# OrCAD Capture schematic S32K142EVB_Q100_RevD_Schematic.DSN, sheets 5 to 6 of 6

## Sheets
5 5. Power Supply/SWD: size C
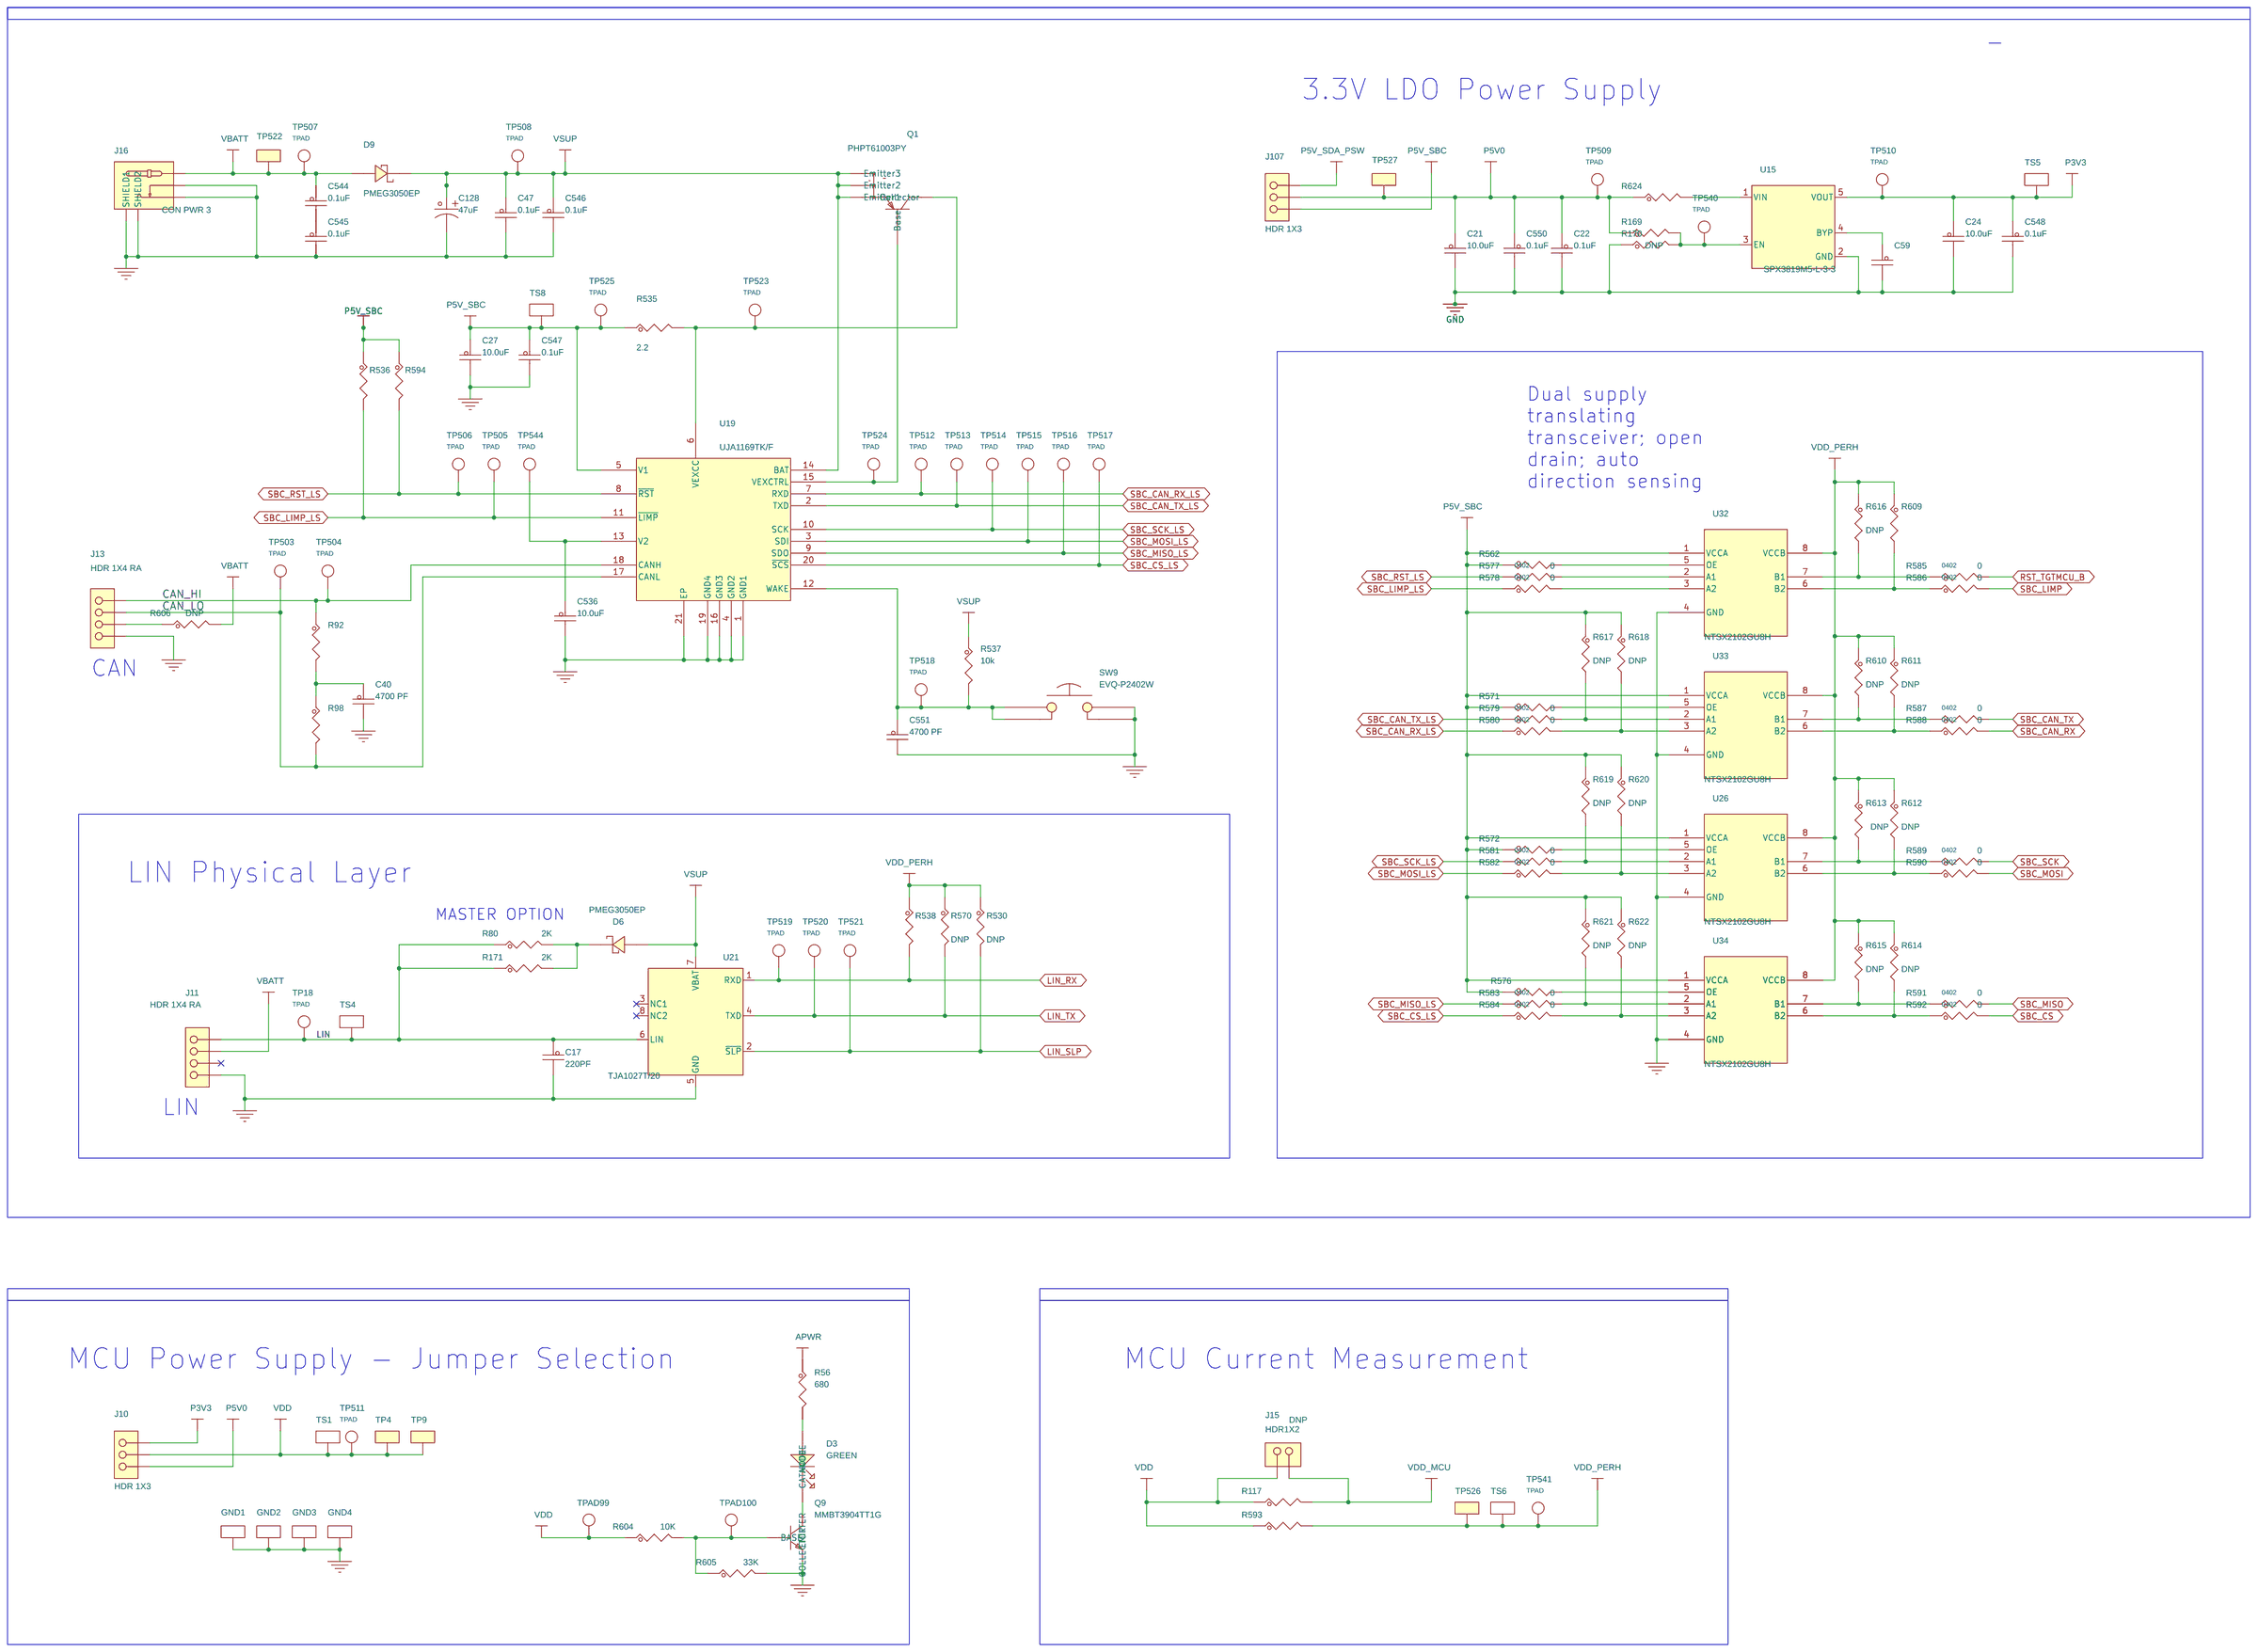
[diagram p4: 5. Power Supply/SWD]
6 6. I/O Headers: size C
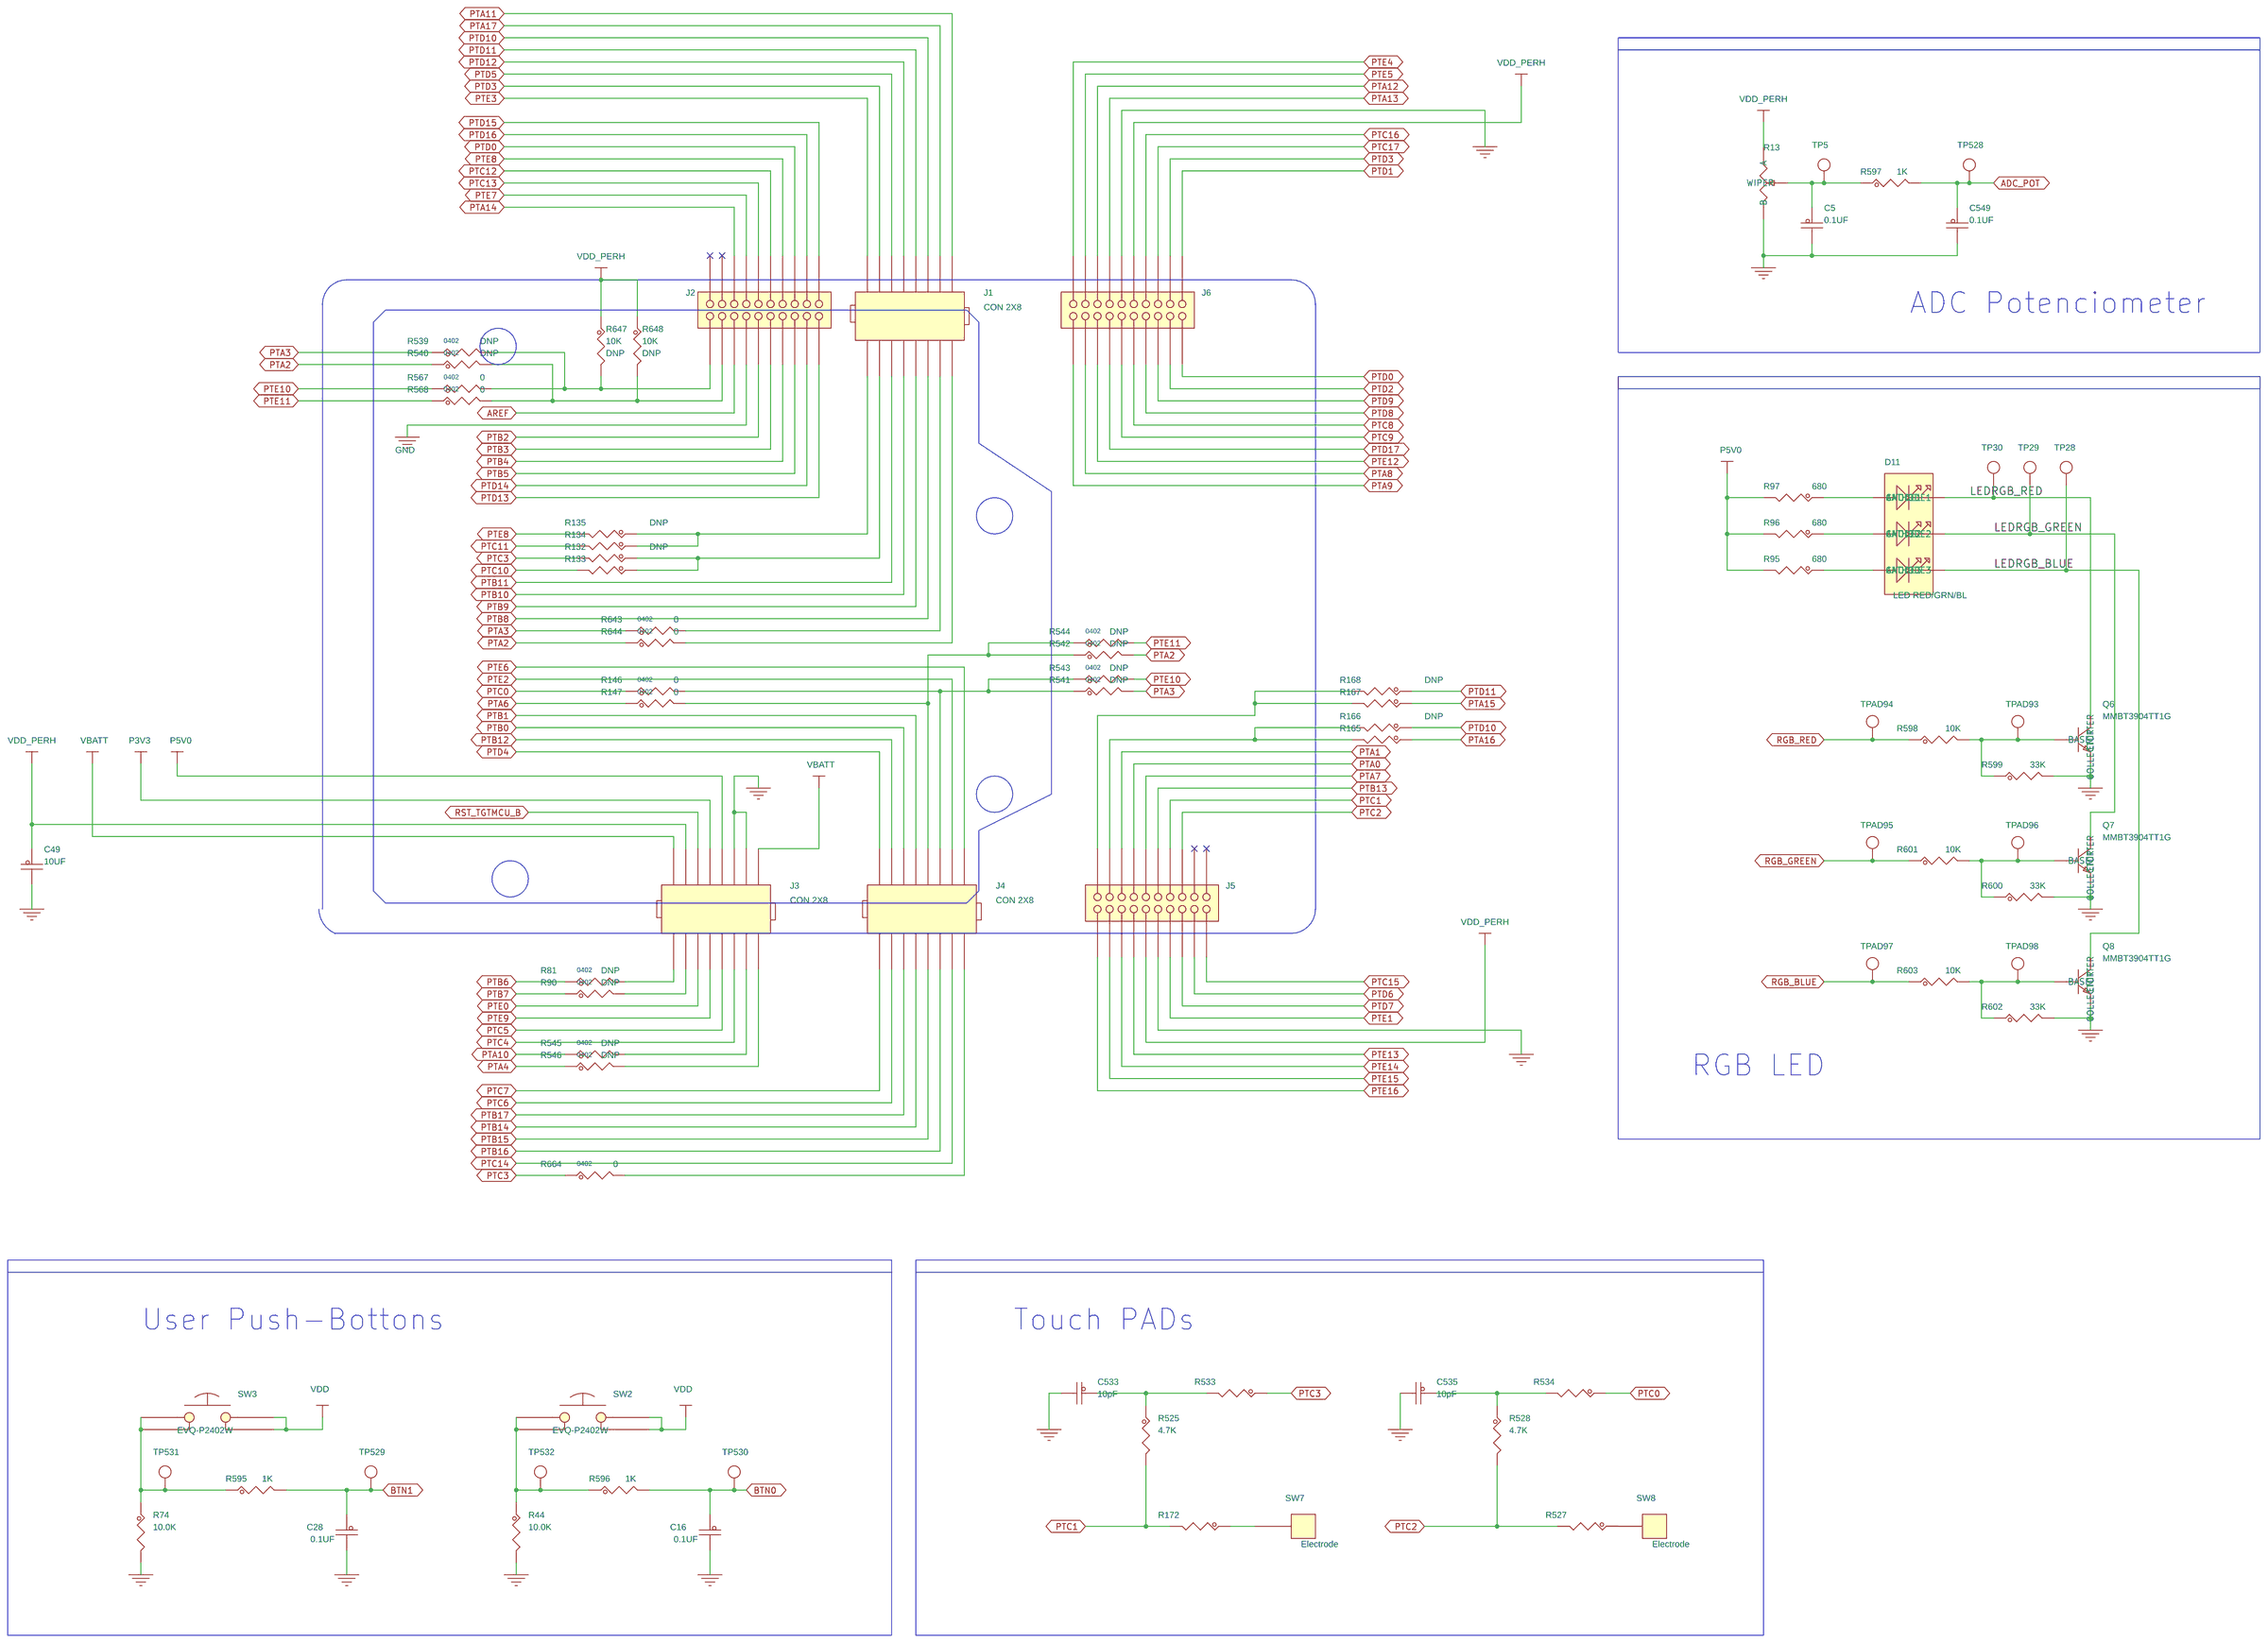
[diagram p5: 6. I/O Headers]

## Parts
sheet 5. Power Supply/SWD
C17  220PF  [CC0603_OV]
C21  10.0uF  [CC0805_OV]
C22  0.1uF  [CC0402_25]
C24  10.0uF  [CC0805_OV]
C27  10.0uF  [CC0805_OV]
C40  4700 PF  [CC0603_OV]
C47  0.1uF  [CC0402_25]
C59  0.01UF  [CC0402_25]
C128  47uF  [cce6p8x6p8]
C536  10.0uF  [CC0805_OV]
C544  0.1uF  [CC0402_25]
C545  0.1uF  [CC0402_25]
C546  0.1uF  [CC0402_25]
C547  0.1uF  [CC0402_25]
C548  0.1uF  [CC0402_25]
C550  0.1uF  [CC0402_25]
C551  4700 PF  [CC0603_OV]
D3  GREEN  [LED_0603]
D6  PMEG3050EP  [sod-128]
D9  PMEG3050EP  [sod-128]
GND1  5006  [tp_th_063]
GND2  5006  [tp_th_063]
GND3  5006  [tp_th_063]
GND4  5006  [tp_th_063]
J10  HDR 1X3  [HDR103_A]
J11  HDR 1X4 RA  [con_hdr_4m_100_th_ra]
J13  HDR 1X4 RA  [con_hdr_4m_100_th_ra]
J15  HDR1X2  [hdr1x2_5p48x2p69]
J16  CON PWR 3  [con3_pwr_jack_th_pj051a]
J107  HDR 1X3  [HDR103_A]
Q1  PHPT61003PY  [LFPAK5_1P27_5X4]
Q9  MMBT3904TT1G  [sc_75]
R56  680  [RC0603_OV]
R80  2K  [RC0805_OV]
R92  60.4  [RC1206_OV]
R98  60.4  [RC1206_OV]
R117  0  [RC0603_OV]
R169  0  [RC0402_25]
R170  0  [RC0402_25]
R171  2K  [RC0805_OV]
R530  4.7K  [RC0603_OV]
R535  2.2  [RC0805_OV]
R536  4.7K  [RC0603_OV]
R537  10k  [RC0805_OV]
R538  4.7K  [RC0603_OV]
R562  4.7K  [RC0402_25]
R570  4.7K  [RC0603_OV]
R571  4.7K  [RC0402_25]
R572  4.7K  [RC0402_25]
R576  4.7K  [RC0402_25]
R577  0  [RC0402_25]
R578  0  [RC0402_25]
R579  0  [RC0402_25]
R580  0  [RC0402_25]
R581  0  [RC0402_25]
R582  0  [RC0402_25]
R583  0  [RC0402_25]
R584  0  [RC0402_25]
R585  0  [RC0402_25]
R586  0  [RC0402_25]
R587  0  [RC0402_25]
R588  0  [RC0402_25]
R589  0  [RC0402_25]
R590  0  [RC0402_25]
R591  0  [RC0402_25]
R592  0  [RC0402_25]
R593  0  [RC0603_OV]
R594  4.7K  [RC0603_OV]
R604  10K  [RC0402_25]
R605  33K  [RC0402_25]
R606  0  [RC0603_OV]
R609  10.0K  [RC0402_25]
R610  10.0K  [RC0402_25]
R611  10.0K  [RC0402_25]
R612  10.0K  [RC0402_25]
R613  10.0K  [RC0402_25]
R614  10.0K  [RC0402_25]
R615  10.0K  [RC0402_25]
R616  10.0K  [RC0402_25]
R617  10.0K  [RC0402_25]
R618  10.0K  [RC0402_25]
R619  10.0K  [RC0402_25]
R620  10.0K  [RC0402_25]
R621  10.0K  [RC0402_25]
R622  10.0K  [RC0402_25]
R624  0  [RC0603_OV]
SW9  EVQ-P2402W  [sw4_spst_4p8X3p6_2p5]
TP4  TEST_POINT  [tp_th_063]
TP9  TEST_POINT  [tp_th_063]
TP18  TPAD_030  [TPAD_030]
TP503  TPAD_030  [TPAD_030]
TP504  TPAD_030  [TPAD_030]
TP505  TPAD_030  [TPAD_030]
TP506  TPAD_030  [TPAD_030]
TP507  TPAD_030  [TPAD_030]
TP508  TPAD_030  [TPAD_030]
TP509  TPAD_030  [TPAD_030]
TP510  TPAD_030  [TPAD_030]
TP511  TPAD_030  [TPAD_030]
TP512  TPAD_030  [TPAD_030]
TP513  TPAD_030  [TPAD_030]
TP514  TPAD_030  [TPAD_030]
TP515  TPAD_030  [TPAD_030]
TP516  TPAD_030  [TPAD_030]
TP517  TPAD_030  [TPAD_030]
TP518  TPAD_030  [TPAD_030]
TP519  TPAD_030  [TPAD_030]
TP520  TPAD_030  [TPAD_030]
TP521  TPAD_030  [TPAD_030]
TP522  TEST_POINT  [tp_th_063]
TP523  TPAD_030  [TPAD_030]
TP524  TPAD_030  [TPAD_030]
TP525  TPAD_030  [TPAD_030]
TP526  TEST_POINT  [tp_th_063]
TP527  TEST_POINT  [tp_th_063]
TP540  TPAD_030  [TPAD_030]
TP541  TPAD_030  [TPAD_030]
TP544  TPAD_030  [TPAD_030]
TPAD99  TPAD_030  [TPAD_030]
TPAD100  TPAD_030  [TPAD_030]
TS1  TESTLOOP  [testpoint_135_070mil]
TS4  TESTLOOP  [testpoint_135_070mil]
TS5  TESTLOOP  [testpoint_135_070mil]
TS6  TESTLOOP  [testpoint_135_070mil]
TS8  TESTLOOP  [testpoint_135_070mil]
U15  SPX3819M5-L-3-3  [SOT23_5S]
U19  UJA1169TK/F  [son20_0p5_3p6x5p6]
U21  TJA1027T/20  [so8_1p27_4x5]
U26  NTSX2102GU8H  [xqfn8_1p45x1p25mm]
U32  NTSX2102GU8H  [xqfn8_1p45x1p25mm]
U33  NTSX2102GU8H  [xqfn8_1p45x1p25mm]
U34  NTSX2102GU8H  [xqfn8_1p45x1p25mm]
sheet 6. I/O Headers
C5  0.1UF  [CC0402_25]
C16  0.1UF  [CC0402_25]
C28  0.1UF  [CC0402_25]
C49  10UF  [CC0805_OV]
C533  10pF  [CC0603_OV]
C535  10pF  [CC0603_OV]
C549  0.1UF  [CC0402_25]
D11  LED RED/GRN/BL  [led6_5x6mm]
J1  CON 2X8  [con2x8_2p54_th]
J2  CON 2X10  [con20_2p54_th]
J3  CON 2X8  [con2x8_2p54_th]
J4  CON 2X8  [con2x8_2p54_th]
J5  CON 2X10  [con20_2p54_th]
J6  CON 2X10  [con20_2p54_th]
Q6  MMBT3904TT1G  [sc_75]
Q7  MMBT3904TT1G  [sc_75]
Q8  MMBT3904TT1G  [sc_75]
R13  5K  [pot3_3352t]
R44  10.0K  [RC0402_25]
R74  10.0K  [RC0402_25]
R81  0  [RC0402_25]
R90  0  [RC0402_25]
R95  680  [RC0603_OV]
R96  680  [RC0603_OV]
R97  680  [RC0603_OV]
R132  0  [RC0603_OV]
R133  0  [RC0603_OV]
R134  0  [RC0603_OV]
R135  0  [RC0603_OV]
R146  0  [RC0402_25]
R147  0  [RC0402_25]
R165  0  [RC0603_OV]
R166  0  [RC0603_OV]
R167  0  [RC0603_OV]
R168  0  [RC0603_OV]
R172  0  [RC0603_OV]
R525  4.7K  [RC0603_OV]
R527  0  [RC0603_OV]
R528  4.7K  [RC0603_OV]
R533  0  [RC0603_OV]
R534  0  [RC0603_OV]
R539  0  [RC0402_25]
R540  0  [RC0402_25]
R541  0  [RC0402_25]
R542  0  [RC0402_25]
R543  0  [RC0402_25]
R544  0  [RC0402_25]
R545  0  [RC0402_25]
R546  0  [RC0402_25]
R567  0  [RC0402_25]
R568  0  [RC0402_25]
R595  1K  [RC0603_OV]
R596  1K  [RC0603_OV]
R597  1K  [RC0603_OV]
R598  10K  [RC0402_25]
R599  33K  [RC0402_25]
R600  33K  [RC0402_25]
R601  10K  [RC0402_25]
R602  33K  [RC0402_25]
R603  10K  [RC0402_25]
R643  0  [RC0402_25]
R644  0  [RC0402_25]
R647  10K  [RC0402_25]
R648  10K  [RC0402_25]
R664  0  [RC0402_25]
SW2  EVQ-P2402W  [sw4_spst_4p8X3p6_2p5]
SW3  EVQ-P2402W  [sw4_spst_4p8X3p6_2p5]
SW7  Electrode  [electrode_sq_15mm]
SW8  Electrode  [electrode_sq_15mm]
TP5  TPAD_030  [TPAD_030]
TP28  TPAD_030  [TPAD_030]
TP29  TPAD_030  [TPAD_030]
TP30  TPAD_030  [TPAD_030]
TP528  TPAD_030  [TPAD_030]
TP529  TPAD_030  [TPAD_030]
TP530  TPAD_030  [TPAD_030]
TP531  TPAD_030  [TPAD_030]
TP532  TPAD_030  [TPAD_030]
TPAD93  TPAD_030  [TPAD_030]
TPAD94  TPAD_030  [TPAD_030]
TPAD95  TPAD_030  [TPAD_030]
TPAD96  TPAD_030  [TPAD_030]
TPAD97  TPAD_030  [TPAD_030]
TPAD98  TPAD_030  [TPAD_030]

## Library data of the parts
C17 = CAP_NP: CAP CER 220PF 50V 10% X7R 0603; AGILE_PN: 150-75200; CAD_APPROVED: Yes; FPLIST: CC0603_OV,CC0603,0603_CC; HEIGHT: 0.9652MM; MFG_NAME01: KEMET; MFG_PN01: C0603C221K5RAC; ROHS: Yes; Tolerance: 10%; VOLTAGE: 50V
C21 C24 C27 C536 = CAP_NP: CAP CER 10UF 16V 10% X7R 0805; AGILE_PN: 150-30139; CAD_APPROVED: Yes; FPLIST: CC0805_OV,CC0805,0805_CC; HEIGHT: 1.27mm; MFG_NAME01: CAPAX TECHNOLOGIES INC.; MFG_PN01: 0805X106K160SNT; ROHS: Yes; Tolerance: 10%; VOLTAGE: 16V
C22 C548 C550 = CAP_NP: CAP CER 0.1uF 50V 10% X7R 0402; AGILE_PN: 150-79069; CAD_APPROVED: Yes; FPLIST: CC0402_25,CC0402_HD,0402_CC; HEIGHT: 0.9 MM; MFG_NAME01: MURATA; MFG_PN01: GCM188R71H104KA57D; ROHS: Yes; Tolerance: 10%; VOLTAGE: 50V
C40 C551 = CAP_NP: CAP CER 4700PF 50V 5% X7R 0603; AGILE_PN: 150-30045; CAD_APPROVED: Yes; FPLIST: CC0603_OV,CC0603,0603_CC; HEIGHT: 1.0MM; MFG_NAME01: AVX; MFG_PN01: 06035C472JAT2A; ROHS: Yes; Tolerance: 5%; VOLTAGE: 50V
C47 C544-C547 = CAP_NP: CAP CER 0.1uF 50V 10% X7R 0402; AGILE_PN: 150-79069; CAD_APPROVED: Yes; FPLIST: CC0402_25,CC0402_HD,0402_CC; HEIGHT: 0.9 MM; MFG_NAME01: TDK; MFG_PN01: C1608X8R1E104K; ROHS: Yes; Tolerance: 10%; VOLTAGE: 50V
C59 = CAP_NP: CAP CER 0.01UF 16V 20% X7R 0402; AGILE_PN: 150-30082; CAD_APPROVED: Yes; FPLIST: CC0402_25,CC0402_HD,0402_CC; HEIGHT: 0.56MM; MFG_NAME01: AVX; MFG_PN01: 0402YC103MAT2A; ROHS: Yes; TOL: 20%; Tolerance: 20%; VOLTAGE: 16V
C128 = CAP_POL: CAP ALEL 47uF 25V 20% -- SMT; AGILE_PN: 150-79138; CAD_APPROVED: Yes; HEIGHT: 6.1MM; MFG_NAME01: NICHICON; MFG_PN01: UUD1E470MCL1GS; ROHS: Yes; Tolerance: 20%; VOLTAGE: 25V
D3 = LED: LED GRN SGL 25MA 0603; AGILE_PN: 370-76549; CAD_APPROVED: Yes; HEIGHT: 0.85MM; MFG_NAME01: KINGBRIGHT; MFG_PN01: KPT-1608SGC; ROHS: Yes
D6 D9 = DIODE_SCHTKY: DIODE SCH RECT 5A 30V AEC-Q101 SOD128; AGILE_PN: 480-78776; CAD_APPROVED: Yes; HEIGHT: 1.1 MM; MFG_NAME01: NXP SEMICONDUCTORS; MFG_PN01: PMEG3050EP,115; ROHS: Yes
GND1 GND2 = TEST_POINT_3: TEST POINT BLK 70X220 MIL TH; AGILE_PN: 210-30155; CAD_APPROVED: Yes; HEIGHT: 5.6MM; MFG_NAME01: Keystone Electronics; ROHS: Yes
GND3 GND4 = TEST_POINT_3: TEST POINT BLK 70X220 MIL TH; AGILE_PN: 210-30155; ASSY_OPT: DNP; CAD_APPROVED: Yes; HEIGHT: 5.6MM; MFG_NAME01: Keystone Electronics; ROHS: Yes
J10 = CONN_HDR_3X1: HDR 1X3 TH 2.54MM SP 344H AU 118L; AGILE_PN: 210-80732; CAD_APPROVED: Yes; HEIGHT: 8.74MM; MFG_NAME01: Shenzhen JXT Technology Co., Ltd.; MFG_PN01: JT254-D180-103-001; ROHS: Yes
J11 J13 = CONN_HDR_4X1: HDR 1X4 TH RA 100MIL SP 268H AU 124L; AGILE_PN: 210-79929; CAD_APPROVED: Yes; HEIGHT: 6.81MM; MFG_NAME01: MOLEX; MFG_PN01: 0022122041; ROHS: Yes
J15 = CONN_HDR_2X1: HDR 1X2 TH 100MIL SP 342H AU 118L; AGILE_PN: 210-80468; ASSY_OPT: DNP; CAD_APPROVED: Yes; HEIGHT: 8.69MM; MFG_NAME01: Shenzhen JXT Technology Co., Ltd.; MFG_PN01: JT254-D180-102-001; ROHS: Yes
J16 = DC_POWER_JACK_SHD: CON 3 PWR JACK RA TH 295H -- NI 98L; AGILE_PN: 210-79945; CAD_APPROVED: Yes; HEIGHT: 7.5MM; MFG_NAME01: CUI INC; MFG_PN01: PJ-051A; ROHS: Yes
J107 = CONN_HDR_3X1: HDR 1X3 TH 2.54MM SP 344H AU 118L; AGILE_PN: 210-80732; CAD_APPROVED: Yes; HEIGHT: 8.74MM; MFG_NAME01: Shenzhen JXT Technology Co., Ltd.; MFG_PN01: JT254-D180-103-001; PRIORITY_PN: 028-00700; ROHS: Yes
Q1 = PMOS_5P: TRAN PNP PWR 3A 100V AEC-Q101 LFPAK56; AGILE_PN: 480-79653; CAD_APPROVED: Yes; HEIGHT: 1.2 MM; MFG_NAME01: NXP SEMICONDUCTORS; MFG_PN01: PHPT61003PYX; ROHS: Yes
Q6-Q9 = NPN: TRAN NPN GEN AMP 200MA 40V AEC-Q101 SC75; AGILE_PN: 480-75477; CAD_APPROVED: Yes; HEIGHT: 0.9 MM; MFG_NAME01: ON SEMICONDUCTOR; ROHS: Yes
R56 R95-R97 = RES: RES MF 680 OHM 1/10W 5% 0603; AGILE_PN: 470-75840; CAD_APPROVED: Yes; FPLIST: RC0603_OV,RC0603,0603_CC; HEIGHT: 0.55MM; MFG_NAME01: BOURNS; MFG_PN01: CR0603-JW-681ELF; ROHS: Yes; Tolerance: 5%
R80 R171 = RES: RES MF 2K 1/8W 1% 0805; AGILE_PN: 470-76341; CAD_APPROVED: Yes; FPLIST: RC0805_OV,RC0805,0805_CC; HEIGHT: 0.65MM; MFG_NAME01: BOURNS; MFG_PN01: CR0805-FX-2001ELF; ROHS: Yes; Tolerance: 1%
R92 R98 = RES: RES MF 60.4 OHM 1/4W 1% 1206; AGILE_PN: 470-78243; CAD_APPROVED: Yes; FPLIST: RC1206_OV,RC1206,1206_CC; HEIGHT: 0.6MM; MFG_NAME01: VISHAY INTERTECHNOLOGY; MFG_PN01: CRCW120660R4FKEA; ROHS: Yes; Tolerance: 1%
R117 R133 R134 R165 R167 R172 R527 R533 R534 R593 R624 = RES: RES MF ZERO OHM 1/10W -- AEC-Q200 0603; AGILE_PN: 470-75407; CAD_APPROVED: Yes; FPLIST: RC0603_OV,RC0603,R603-X2,0603_CC; HEIGHT: 0.6MM; MFG_NAME01: KOA SPEER; MFG_PN01: RK73Z1JTTD; ROHS: Yes; Tolerance: 1%
R169 = RES: RES MF ZERO OHM 1/16W -- AEC-Q200 0402; AGILE_PN: 470-80742; CAD_APPROVED: Yes; FPLIST: RC0402_25,RC0402_HD,0402_CC; HEIGHT: 0.45 MM; MFG_NAME01: VISHAY INTERTECHNOLOGY; MFG_PN01: CRCW04020000Z0ED; ROHS: Yes
R170 = RES: RES MF ZERO OHM 1/16W -- AEC-Q200 0402; AGILE_PN: 470-80742; ASSY_OPT: DNP; CAD_APPROVED: Yes; FPLIST: RC0402_25,RC0402_HD,0402_CC; HEIGHT: 0.45 MM; MFG_NAME01: VISHAY INTERTECHNOLOGY; MFG_PN01: CRCW04020000Z0ED; ROHS: Yes
R530 R570 = RES: RES MF 4.7K 1/10W 5% 0603; AGILE_PN: 470-75414; ASSY_OPT: DNP; CAD_APPROVED: Yes; FPLIST: RC0603_OV,RC0603,0603_CC; HEIGHT: 0.55 MM; MFG_NAME01: VISHAY INTERTECHNOLOGY; MFG_PN01: CRCW06034K70JNEA; ROHS: Yes; Tolerance: 5%
R535 = RES: RES MF 2.20 OHM 1/8W 1% 0805; AGILE_PN: 470-76034; CAD_APPROVED: Yes; FPLIST: RC0805_OV,RC0805,0805_CC; HEIGHT: 0.65MM; MFG_NAME01: BOURNS; MFG_PN01: CRL0805-FW-2R20ELF; ROHS: Yes; Tolerance: 1%
R536 R538 R594 = RES: RES MF 4.7K 1/10W 5% 0603; AGILE_PN: 470-75414; CAD_APPROVED: Yes; FPLIST: RC0603_OV,RC0603,0603_CC; HEIGHT: 0.55 MM; MFG_NAME01: VISHAY INTERTECHNOLOGY; MFG_PN01: CRCW06034K70JNEA; ROHS: Yes; Tolerance: 5%
R537 = RES: RES MF 10.0K 1/8W 0.1% 0805; AGILE_PN: 470-80065; CAD_APPROVED: Yes; FPLIST: RC0805_OV,RC0805,0805_CC; HEIGHT: 0.65 MM; MFG_NAME01: BOURNS; MFG_PN01: CRT0805-BY-1002ELF; ROHS: Yes; Tolerance: 0.1%
R562 R571 R572 R576 = RES: RES MF 4.7K 1/16W 5% 0402; AGILE_PN: 470-75626; CAD_APPROVED: Yes; FPLIST: RC0402_25,RC0402_HD,0402_CC; HEIGHT: 0.41mm; MFG_NAME01: KOA SPEER; MFG_PN01: RK73B1ETTP472J; ROHS: Yes; SIGNAL_MODEL: DEFAULT_RESISTOR_4700OHM_2_1; TOL: 1%; Tolerance: 5%
R146 R147 R567 R568 R577-R592 R643 R644 R664 = RES: RES MF ZERO OHM 1/16W -- AEC-Q200 0402; AGILE_PN: 470-80742; CAD_APPROVED: Yes; FPLIST: RC0402_25,RC0402_HD,0402_CC; HEIGHT: 0.45 MM; MFG_NAME01: VISHAY INTERTECHNOLOGY; MFG_PN01: CRCW04020000Z0ED; PCKG: 0402; ROHS: Yes
R598 R601 R603 R604 = RES: RES MF 10K 1/8W 1% AEC-Q200 0402; AGILE_PN: 470-80881; CAD_APPROVED: Yes; FPLIST: RC0402_25,RC0402_HD,0402_CC; HEIGHT: 0.4MM; MFG_NAME01: VISHAY INTERTECHNOLOGY; MFG_PN01: CRCW040210K0FKEDHP; ROHS: Yes; Tolerance: 1%
R599 R600 R602 R605 = RES: RES MF 33K 1/16W 5% 0402; AGILE_PN: 470-75615; CAD_APPROVED: Yes; FPLIST: RC0402_25,RC0402_HD,0402_CC; HEIGHT: 0.45mm; MFG_NAME01: SMEC; MFG_PN01: RC73L2Z333JTF; ROHS: Yes; Tolerance: 5%
R132 R135 R166 R168 R606 = RES: RES MF ZERO OHM 1/10W -- AEC-Q200 0603; AGILE_PN: 470-75407; ASSY_OPT: DNP; CAD_APPROVED: Yes; FPLIST: RC0603_OV,RC0603,R603-X2,0603_CC; HEIGHT: 0.6MM; MFG_NAME01: KOA SPEER; MFG_PN01: RK73Z1JTTD; ROHS: Yes; Tolerance: 1%
R609 = RES: RES MF 10.0K 1/16W 1% AEC-Q200 0402; AGILE_PN: 470-75416; CAD_APPROVED: Yes; FPLIST: RC0402_25,RC0402_HD,0402_CC; HEIGHT: 0.4MM; MFG_NAME01: KOA SPEER; MFG_PN01: RK73H1ETTP1002F; PRIORITY_PN: 006-00552; ROHS: Yes; SIGNAL_MODEL: DEFAULT_RESISTOR_10000OHM_2_1; TOL: 5%; Tolerance: 1%
R610-R622 = RES: RES MF 10.0K 1/16W 1% AEC-Q200 0402; AGILE_PN: 470-75416; ASSY_OPT: DNP; CAD_APPROVED: Yes; FPLIST: RC0402_25,RC0402_HD,0402_CC; HEIGHT: 0.4MM; MFG_NAME01: KOA SPEER; MFG_PN01: RK73H1ETTP1002F; PRIORITY_PN: 006-00552; ROHS: Yes; SIGNAL_MODEL: DEFAULT_RESISTOR_10000OHM_2_1; TOL: 5%; Tolerance: 1%
SW2 SW3 SW9 = EDGE_MOUNT_PB_SW_2: SW SPST PB NO 0.02A 15V SMT; AGILE_PN: 510-77992; CAD_APPROVED: Yes; HEIGHT: 2.7 MM; MFG_NAME01: Panasonic; ROHS: Yes
TP4 TP9 TP522 TP526 TP527 = TEST_POINT_0: TEST POINT RED 70X220 MIL TH; AGILE_PN: 210-30156; CAD_APPROVED: Yes; HEIGHT: 5.59MM; MFG_NAME01: KEYSTONE ELECTRONICS; MFG_PN01: 5005; ROHS: Yes
TP18 TP503-TP521 TP523-TP525 TP540 TP541 TP544 = TESTLOOP: TEST POINT PAD 30MIL DIA SMT, NO PART TO ORDER; AGILE_PN: 211-76642; CAD_APPROVED: Yes; HEIGHT: 0.1MM; MFG_NAME01: NOTACOMPONENT; MFG_PN01: NOTACOMPONENT; NOTE: TPAD; ROHS: Yes
TP28-TP30 TPAD93-TPAD100 = TestLoop: TEST POINT PAD 30MIL DIA SMT, NO PART TO ORDER; AGILE_PN: 211-76642; CAD_APPROVED: Yes; HEIGHT: 0.1MM; MFG_NAME01: NOTACOMPONENT; MFG_PN01: NOTACOMPONENT; ROHS: Yes
TS1 TS4-TS6 TS8 = TEST_POINT_4: TEST POINT PAD SIZE 3.4MM X 1.8MM SMT; AGILE_PN: 211-75906; CAD_APPROVED: Yes; HEIGHT: 1.53 MM; MFG_NAME01: KEYSTONE ELECTRONICS; MFG_PN01: 5015; PRIORITY_PN: 922-00014; ROHS: Yes
U15 = SPX3819M5_FIX_0: IC VREG LDO 3.3V 500MA 2.5-16V SOT-23-5; AGILE_PN: 315-79574; CAD_APPROVED: Yes; HEIGHT: 1.45 MM; MFG_NAME01: EXAR; ROHS: Yes
U19 = UJA1169TKF_3: IC XCVR CAN/FD SBC 5V AEC-Q100 HVSON20; AGILE_PN: 315-80898; CAD_APPROVED: Yes; HEIGHT: 1 MM; MFG_NAME01: NXP SEMICONDUCTORS; MFG_PN01: UJA1169TK/FZ; ROHS: Yes
U21 = TJA1027T_8P: IC XCVR LIN 5-18V AEC-Q100 SOIC8; AGILE_PN: 312-81255; CAD_APPROVED: Yes; HEIGHT: 1.75MM; MFG_NAME01: NXP SEMICONDUCTORS; MFG_PN01: TJA1027T/20,118; ROHS: Yes
U26 U32-U34 = NTSX2102GU8H_0: IC DUAL SUPPLY XCVR 50 MBPS 5.5V XQFN8; AGILE_PN: 312-80763; CAD_APPROVED: Yes; HEIGHT: 0.5MM; MFG_NAME01: NXP Semiconductors; ROHS: Yes; VOLTAGE: 5.5V
C5 C549 = CAP_NP: CAP CER 0.1UF 10V 10% X5R 0402; AGILE_PN: 150-75634; CAD_APPROVED: Yes; FPLIST: CC0402_25,CC0402_HD,0402_CC; HEIGHT: 0.64MM; MFG_NAME01: KEMET; MFG_PN01: C0402C104K8PAC; ROHS: Yes; SIGNAL_MODEL: DEFAULT_CAPACITOR_100000pF_2_1; TOL: 10%; Tolerance: 10%; VOLTAGE: 10V
C16 C28 = CAP_NP: CAP CER 0.1UF 10V 10% X5R 0402; AGILE_PN: 150-75634; CAD_APPROVED: Yes; FPLIST: CC0402_25,CC0402_HD,0402_CC; HEIGHT: 0.64MM; MFG_NAME01: KEMET; MFG_PN01: C0402C104K8PAC; PRIORITY_PN: 021-00169; ROHS: Yes; SIGNAL_MODEL: DEFAULT_CAPACITOR_100000pF_2_1; Tolerance: 10%; VOLTAGE: 10V
C49 = CAP_NP: CAP CER 10UF 10V 10% X7R 0805; AGILE_PN: 150-78501; CAD_APPROVED: Yes; FPLIST: CC0603_OV,CC0603,0603_CC; HEIGHT: 1.4MM; MFG_NAME01: Murata; MFG_PN01: GRM21BR71A106KE51L; ROHS: Yes; Tolerance: 10%; VOLTAGE: 10V
C533 C535 = CAP_NP: CAP CER 10PF 50V 10% X7R 0603; AGILE_PN: 150-78432; CAD_APPROVED: Yes; FPLIST: CC0603_OV,CC0603,0603_CC; HEIGHT: 0.9MM; MFG_NAME01: AVX; MFG_PN01: 06035C100KAT2A; ROHS: Yes; TOL: 10%; Tolerance: 10%; VOLTAGE: 50V
D11 = LED_TRI_COLOR: LED RED/GRN/BL SGL 3-IN-1 50mA SMT; AGILE_PN: 370-76661; CAD_APPROVED: Yes; HEIGHT: 2.6 MM; MFG_NAME01: Cree, Inc; MFG_PN01: CLP6C-FKB-CM1Q1H1BB7R3R3; ROHS: Yes
J1 J3 J4 = HDR_2X8_M: CON 2X8 SKT TH 100MIL CTR 340H SN 118L; AGILE_PN: 210-80983; CAD_APPROVED: Yes; HEIGHT: 8.65MM; MFG_NAME01: Shenzhen JXT Technology Co., Ltd.; MFG_PN01: JT254-D180-850-208-001; ROHS: Yes
J2 J5 J6 = CONN_HDR_10X2: CON 2X10 SKT TH 100MIL CTR 340H SN 118L; AGILE_PN: 210-80982; CAD_APPROVED: Yes; HEIGHT: 8.65MM; MFG_NAME01: Shenzhen JXT Technology Co., Ltd.; MFG_PN01: JT254-D180-850-210-001; ROHS: Yes
R13 = POT: RES POT 5K 1/2W 20% TH; AGILE_PN: 470-80115; CAD_APPROVED: Yes; HEIGHT: 4.32 MM; MFG_NAME01: BOURNS; MFG_PN01: 3352T-1-502LF; ROHS: Yes; TOL: 20%; Tolerance: 20%
R44 R74 = RES: RES MF 10.0K 1/16W 1% AEC-Q200 0402; AGILE_PN: 470-75416; CAD_APPROVED: Yes; FPLIST: RC0402_25,RC0402_HD,0402_CC; HEIGHT: 0.4MM; MFG_NAME01: KOA SPEER; MFG_PN01: RK73H1ETTP1002F; PRIORITY_PN: 006-00552; ROHS: Yes; SIGNAL_MODEL: DEFAULT_RESISTOR_10000OHM_2_1; TOL: 1%; Tolerance: 1%
R81 R90 R539-R546 = RES: RES MF ZERO OHM 1/16W -- AEC-Q200 0402; AGILE_PN: 470-80742; ASSY_OPT: DNP; CAD_APPROVED: Yes; FPLIST: RC0402_25,RC0402_HD,0402_CC; HEIGHT: 0.45 MM; MFG_NAME01: VISHAY INTERTECHNOLOGY; MFG_PN01: CRCW04020000Z0ED; PCKG: 0402; ROHS: Yes
R525 R528 = RES: RES MF 4.7K 1/10W 0.1% AEC-Q200 0603; AGILE_PN: 470-80811; CAD_APPROVED: Yes; FPLIST: RC0603_OV,RC0603,0603_CC; HEIGHT: 0.55MM; MFG_NAME01: VISHAY INTERTECHNOLOGY; MFG_PN01: TNPW06034K70BEEA; ROHS: Yes; Tolerance: 0.1%
R595-R597 = RES: RES MF 1K 1/10W 1% AEC-Q200 0603; AGILE_PN: 470-81441; CAD_APPROVED: Yes; FPLIST: RC0603_OV,RC0603,0603_CC; HEIGHT: 0.55 MM; MFG_NAME01: Yageo; MFG_PN01: AT0603FRE071KL; ROHS: Yes; Temp_Range: – 55 °C to +155 °C; Tolerance: 1%
R647 R648 = RES: RES MF 10K 1/8W 1% AEC-Q200 0402; AGILE_PN: 470-80881; ASSY_OPT: DNP; CAD_APPROVED: Yes; FPLIST: RC0402_25,RC0402_HD,0402_CC; HEIGHT: 0.4MM; MFG_NAME01: VISHAY INTERTECHNOLOGY; MFG_PN01: CRCW040210K0FKEDHP; ROHS: Yes; Tolerance: 1%
SW7 SW8 = ELECTRODE: Capacitive Single Electrode 15MM x 15MM (not a part to order); AGILE_PN: 510-76938; CAD_APPROVED: Yes; FPLIST: electrode_sq_15mm,electrode_sq_15mm_cust; HEIGHT: 0MM; MFG_NAME01: Freescale; MFG_PN01: Single Electrode 15MM x 15MM; ROHS: Yes
TP5 TP528-TP532 = TESTLOOP: TEST POINT PAD 30MIL DIA SMT, NO PART TO ORDER; AGILE_PN: 211-76642; CAD_APPROVED: Yes; HEIGHT: 0.1MM; MFG_NAME01: NOTACOMPONENT; MFG_PN01: NOTACOMPONENT; ROHS: Yes

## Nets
GND: C5.2 C16.2 C17.2 C21.2 C22.2 C24.2 C27.2 C28.2 C40.2 C47.2 C49.2 C59.2 C128.2 C533.2 C535.2 C536.2 C545.2 C546.2 C547.2 C548.2 C549.2 C550.2 C551.2 GND1.1 GND2.1 GND3.1 GND4.1 J2.13 J3.11 J3.13 J5.12 J6.12 J11.4 J13.4 J16.2 J16.3 J16.SH1(SHIELD1) J16.SH2(SHIELD2) Q6.2(EMITTER) Q7.2(EMITTER) Q8.2(EMITTER) Q9.2(EMITTER) R13.3(B) R44.2 R74.2 R170.1 R599.2 R600.2 R602.2 R605.2 SW9.2 SW9.4 U15.2(GND) U19.1(GND1) U19.4(GND2) U19.16(GND3) U19.19(GND4) U19.21(EP) U21.5(GND) U26.4(GND) U32.4(GND) U33.4(GND) U34.4(GND) ; also on sheet 1 2
P3V3: C24.1 C548.1 J3.7 J10.1 TP510.1(Pin1) TS5.1 U15.5(VOUT)
P5V0: C21.1 C22.1 C550.1 J3.9 J10.3 J107.2 R56.1 R95.2 R96.2 R97.2 R169.1 R624.1 TP509.1(Pin1) TP527.1
P5V_SBC: C27.1 C547.1 J107.1 R535.1 R536.1 R562.1 R571.1 R572.1 R576.1 R594.1 R617.1 R618.1 R619.1 R620.1 R621.1 R622.1 TP525.1(Pin1) TS8.1 U19.5(V1) U26.1(VCCA) U32.1(VCCA) U33.1(VCCA) U34.1(VCCA)
P5V_SDA_PSW: J107.3 ; also on sheet 1
VBATT: C544.1 D9.A J3.1 J3.15 J11.2 J16.1 R606.2 TP507.1(Pin1) TP522.1
VDD: J10.2 J15.2 R117.1 R593.1 R604.1 SW2.2 SW2.4 SW3.2 SW3.4 TP4.1 TP9.1 TP511.1(Pin1) TPAD99.1(Pin1) TS1.1 ; also on sheet 1 2
VDD_MCU: J15.1 R117.2 ; also on sheet 2
VDD_PERH: C49.1 J3.3 J5.10 J6.10 R13.1(A) R530.1 R538.1 R570.1 R593.2 R609.1 R610.1 R611.1 R612.1 R613.1 R614.1 R615.1 R616.1 R647.1 R648.1 TP526.1 TP541.1(Pin1) TS6.1 U26.8(VCCB) U32.8(VCCB) U33.8(VCCB) U34.8(VCCB)
ADC_POT: C549.1 R597.2 TP528.1(Pin1) ; also on sheet 2
AREF: J2.15 ; also on sheet 2
BTN0: C16.1 R596.2 TP530.1(Pin1) ; also on sheet 2
BTN1: C28.1 R595.2 TP529.1(Pin1) ; also on sheet 2
CAN_HI: J13.1 R92.1 TP504.1(Pin1) U19.18(CANH)
CAN_LO: J13.2 R98.2 TP503.1(Pin1) U19.17(CANL)
LEDRGB_BLUE: D11.C3(CATHODE3) Q8.3(COLLECTOR) TP28.1(Pin1)
LEDRGB_GREEN: D11.C2(CATHODE2) Q7.3(COLLECTOR) TP29.1(Pin1)
LEDRGB_RED: D11.C1(CATHODE1) Q6.3(COLLECTOR) TP30.1(Pin1)
LIN: C17.1 J11.1 R80.1 R171.1 TP18.1(Pin1) TS4.1 U21.6(LIN)
LIN_RX: R538.2 TP519.1(Pin1) U21.1(RXD) ; also on sheet 2
LIN_SLP: R530.2 TP521.1(Pin1) U21.2(~{SLP}) ; also on sheet 2
LIN_TX: R570.2 TP520.1(Pin1) U21.4(TXD) ; also on sheet 2
PTA0: J5.7 ; also on sheet 2
PTA1: J5.5 ; also on sheet 2
PTA2: R540.1 R542.2 R644.1 ; also on sheet 2
PTA3: R539.1 R541.2 R643.1 ; also on sheet 2
PTA4: R546.1 ; also on sheet 2
PTA6: R147.1 ; also on sheet 2
PTA7: J5.9 ; also on sheet 2
PTA8: J6.17 ; also on sheet 2
PTA9: J6.19 ; also on sheet 2
PTA10: R545.1 ; also on sheet 2
PTA11: J1.2 ; also on sheet 2
PTA12: J6.16 ; also on sheet 2
PTA13: J6.14 ; also on sheet 2
PTA14: J2.16 ; also on sheet 2
PTA15: R167.1 ; also on sheet 2
PTA16: R165.1 ; also on sheet 2
PTA17: J1.4 ; also on sheet 2
PTB0: J4.5 ; also on sheet 2
PTB1: J4.7 ; also on sheet 2
PTB2: J2.11 ; also on sheet 2
PTB3: J2.9 ; also on sheet 2
PTB4: J2.7 ; also on sheet 2
PTB5: J2.5 ; also on sheet 2
PTB6: R81.1 ; also on sheet 2
PTB7: R90.1 ; also on sheet 2
PTB8: J1.5 ; also on sheet 2
PTB9: J1.7 ; also on sheet 2
PTB10: J1.9 ; also on sheet 2
PTB11: J1.11 ; also on sheet 2
PTB12: J4.3 ; also on sheet 2
PTB13: J5.11 ; also on sheet 2
PTB14: J4.8 ; also on sheet 2
PTB15: J4.10 ; also on sheet 2
PTB16: J4.12 ; also on sheet 2
PTB17: J4.6 ; also on sheet 2
PTC0: R146.1 R534.1 ; also on sheet 2
PTC1: J5.13 R172.2 R525.2 ; also on sheet 2
PTC2: J5.15 R527.2 R528.2 ; also on sheet 2
PTC3: R132.2 R533.1 R664.1 ; also on sheet 2
PTC4: J3.12 ; also on sheet 2
PTC5: J3.10 ; also on sheet 2
PTC6: J4.4 ; also on sheet 2
PTC7: J4.2 ; also on sheet 2
PTC8: J6.9 ; also on sheet 2
PTC9: J6.11 ; also on sheet 2
PTC10: R133.2 ; also on sheet 2
PTC11: R134.2 ; also on sheet 2
PTC12: J2.10 ; also on sheet 2
PTC13: J2.12 ; also on sheet 2
PTC14: J4.14 ; also on sheet 2
PTC15: J5.20 ; also on sheet 2
PTC16: J6.8 ; also on sheet 2
PTC17: J6.6 ; also on sheet 2
PTD0: J2.6 J6.1 ; also on sheet 2
PTD1: J6.2 ; also on sheet 2
PTD2: J6.3 ; also on sheet 2
PTD3: J1.14 J6.4 ; also on sheet 2
PTD4: J4.1 ; also on sheet 2
PTD5: J1.12 ; also on sheet 2
PTD6: J5.18 ; also on sheet 2
PTD7: J5.16 ; also on sheet 2
PTD8: J6.7 ; also on sheet 2
PTD9: J6.5 ; also on sheet 2
PTD10: J1.6 R166.1 ; also on sheet 2
PTD11: J1.8 R168.1 ; also on sheet 2
PTD12: J1.10 ; also on sheet 2
PTD13: J2.1 ; also on sheet 2
PTD14: J2.3 ; also on sheet 2
PTD15: J2.2 ; also on sheet 2
PTD16: J2.4 ; also on sheet 2
PTD17: J6.13 ; also on sheet 2
PTE0: J3.6 ; also on sheet 2
PTE1: J5.14 ; also on sheet 2
PTE2: J4.13 ; also on sheet 2
PTE3: J1.16 ; also on sheet 2
PTE4: J6.20 ; also on sheet 2
PTE5: J6.18 ; also on sheet 2
PTE6: J4.15 ; also on sheet 2
PTE7: J2.14 ; also on sheet 2
PTE8: J2.8 R135.2 ; also on sheet 2
PTE9: J3.8 ; also on sheet 2
PTE10: R543.2 R567.1 ; also on sheet 2
PTE11: R544.2 R568.1 ; also on sheet 2
PTE12: J6.15 ; also on sheet 2
PTE13: J5.8 ; also on sheet 2
PTE14: J5.6 ; also on sheet 2
PTE15: J5.4 ; also on sheet 2
PTE16: J5.2 ; also on sheet 2
RGB_BLUE: R603.1 TPAD97.1(Pin1) ; also on sheet 2
RGB_GREEN: R601.1 TPAD95.1(Pin1) ; also on sheet 2
RGB_RED: R598.1 TPAD94.1(Pin1) ; also on sheet 2
RST_TGTMCU_B: J3.5 R585.2 ; also on sheet 1 2
SBC_CAN_RX: R588.2 ; also on sheet 2
SBC_CAN_RX_LS: R580.1 TP512.1(Pin1) U19.7(RXD)
SBC_CAN_TX: R587.2 ; also on sheet 2
SBC_CAN_TX_LS: R579.1 TP513.1(Pin1) U19.2(TXD)
SBC_CS: R592.2 ; also on sheet 2
SBC_CS_LS: R584.1 TP517.1(Pin1) U19.20(~{SCS})
SBC_LIMP: R586.2 ; also on sheet 2
SBC_LIMP_LS: R536.2 R578.1 TP505.1(Pin1) U19.11(~{LIMP})
SBC_MISO: R591.2 ; also on sheet 2
SBC_MISO_LS: R583.1 TP516.1(Pin1) U19.9(SDO)
SBC_MOSI: R590.2 ; also on sheet 2
SBC_MOSI_LS: R582.1 TP515.1(Pin1) U19.3(SDI)
SBC_RST_LS: R577.1 R594.2 TP506.1(Pin1) U19.8(~{RST})
SBC_SCK: R589.2 ; also on sheet 2
SBC_SCK_LS: R581.1 TP514.1(Pin1) U19.10(SCK)
VSUP: C47.1 C128.1 C546.1 D6.A D9.C Q1.1(Emitter1) Q1.2(Emitter2) Q1.3(Emitter3) R537.1 TP508.1(Pin1) U19.14(BAT) U21.7(VBAT)
N20187731: D11.A3(ANODE3) R95.1
N20187747: D11.A2(ANODE2) R96.1
N20224636: C5.1 R13.2(WIPER) R597.1 TP5.1(Pin1)
N20296072: R44.1 R596.1 SW2.1 SW2.3 TP532.1(Pin1)
N20296289: R74.1 R595.1 SW3.1 SW3.3 TP531.1(Pin1)
N20296614: D11.A1(ANODE1) R97.1
N20337946: J5.3 R165.2 R166.2
N20338949: J5.1 R167.2 R168.2
N20341657: J1.13 R132.1 R133.1
N20341806: J1.15 R134.1 R135.1
N20342040: J2.19 R539.2 R567.2 R647.2
N20342083: J2.17 R540.2 R568.2 R648.2
N20344687: J4.11 R146.2 R541.1 R543.1
N20344693: J4.9 R147.2 R542.1 R544.1
N20408163: R169.2 R170.2 TP540.1(Pin1) U15.3(EN)
N20408770: C59.1 U15.4(BYP)
N20447644: J1.1 R644.2
N20447648: J1.3 R643.2
N20483325: J3.2 R81.2
N20483330: J3.4 R90.2
N20483362: J3.14 R545.2
N20483368: J3.16 R546.2
N20484569: J4.16 R664.2
N20487643: C533.1 R525.1 R533.2
N20487701: R527.1 SW8.1
N20487722: C535.1 R528.1 R534.2
N20498073: Q1.4(Base) TP524.1(Pin1) U19.15(VEXCTRL)
N20519466: C536.1 TP544.1(Pin1) U19.13(V2)
N20529258: D6.C R80.2 R171.2
N20532266: Q1.5(Collector) R535.2 TP523.1(Pin1) U19.6(VEXCC)
N20533540: R172.1 SW7.1
N20537015: C551.1 R537.2 SW9.1 SW9.3 TP518.1(Pin1) U19.12(WAKE)
N20615858: R590.1 R612.2 U26.6(B2)
N20615860: R589.1 R613.2 U26.7(B1)
N20628442: R585.1 R616.2 U32.7(B1)
N20629726: R577.2 U32.2(A1)
N20726302: R578.2 U32.3(A2)
N20726411: R586.1 R609.2 U32.6(B2)
N20727622: R562.2 U32.5(OE)
N20728836: C40.1 R92.2 R98.1
N20751108: R571.2 U33.5(OE)
N20751111: R587.1 R610.2 U33.7(B1)
N20751112: R588.1 R611.2 U33.6(B2)
N20754157: R572.2 U26.5(OE)
N20757133: R591.1 R615.2 U34.7(B1)
N20757185: R592.1 R614.2 U34.6(B2)
N20757257: R576.2 U34.5(OE)
N20757373: R579.2 R617.2 U33.2(A1)
N20757398: R580.2 R618.2 U33.3(A2)
N20757820: R581.2 R619.2 U26.2(A1)
N20757845: R582.2 R620.2 U26.3(A2)
N20758005: R583.2 R621.2 U34.2(A1)
N20758031: R584.2 R622.2 U34.3(A2)
N20759089: D3.A(ANODE) R56.2
N20788275: Q6.1(BASE) R598.2 R599.1 TPAD93.1(Pin1)
N20788431: Q7.1(BASE) R600.1 R601.2 TPAD96.1(Pin1)
N20788562: Q8.1(BASE) R602.1 R603.2 TPAD98.1(Pin1)
N20797138: Q9.1(BASE) R604.2 R605.1 TPAD100.1(Pin1)
N20798434: D3.C(CATHODE) Q9.3(COLLECTOR)
N20799004: J13.3 R606.1
N20809848: C544.2 C545.1
N20829527: R624.2 U15.1(VIN)

Not connected (* = marked no-connect by the designer): J2 18* 20*; J5 17* 19*; J11 3*; U21 3(NC1)* 8(NC2)*

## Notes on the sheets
sheet 5
- 3.3V LDO Power Supply
- Dual supply
  translating
  transceiver; open
  drain; auto
  direction sensing
- CAN
- LIN Physical Layer
- MASTER OPTION
- LIN
- MCU Power Supply - Jumper Selection
- MCU Current Measurement
sheet 6
- ADC Potenciometer
- RGB LED
- User Push-Bottons
- Touch PADs
